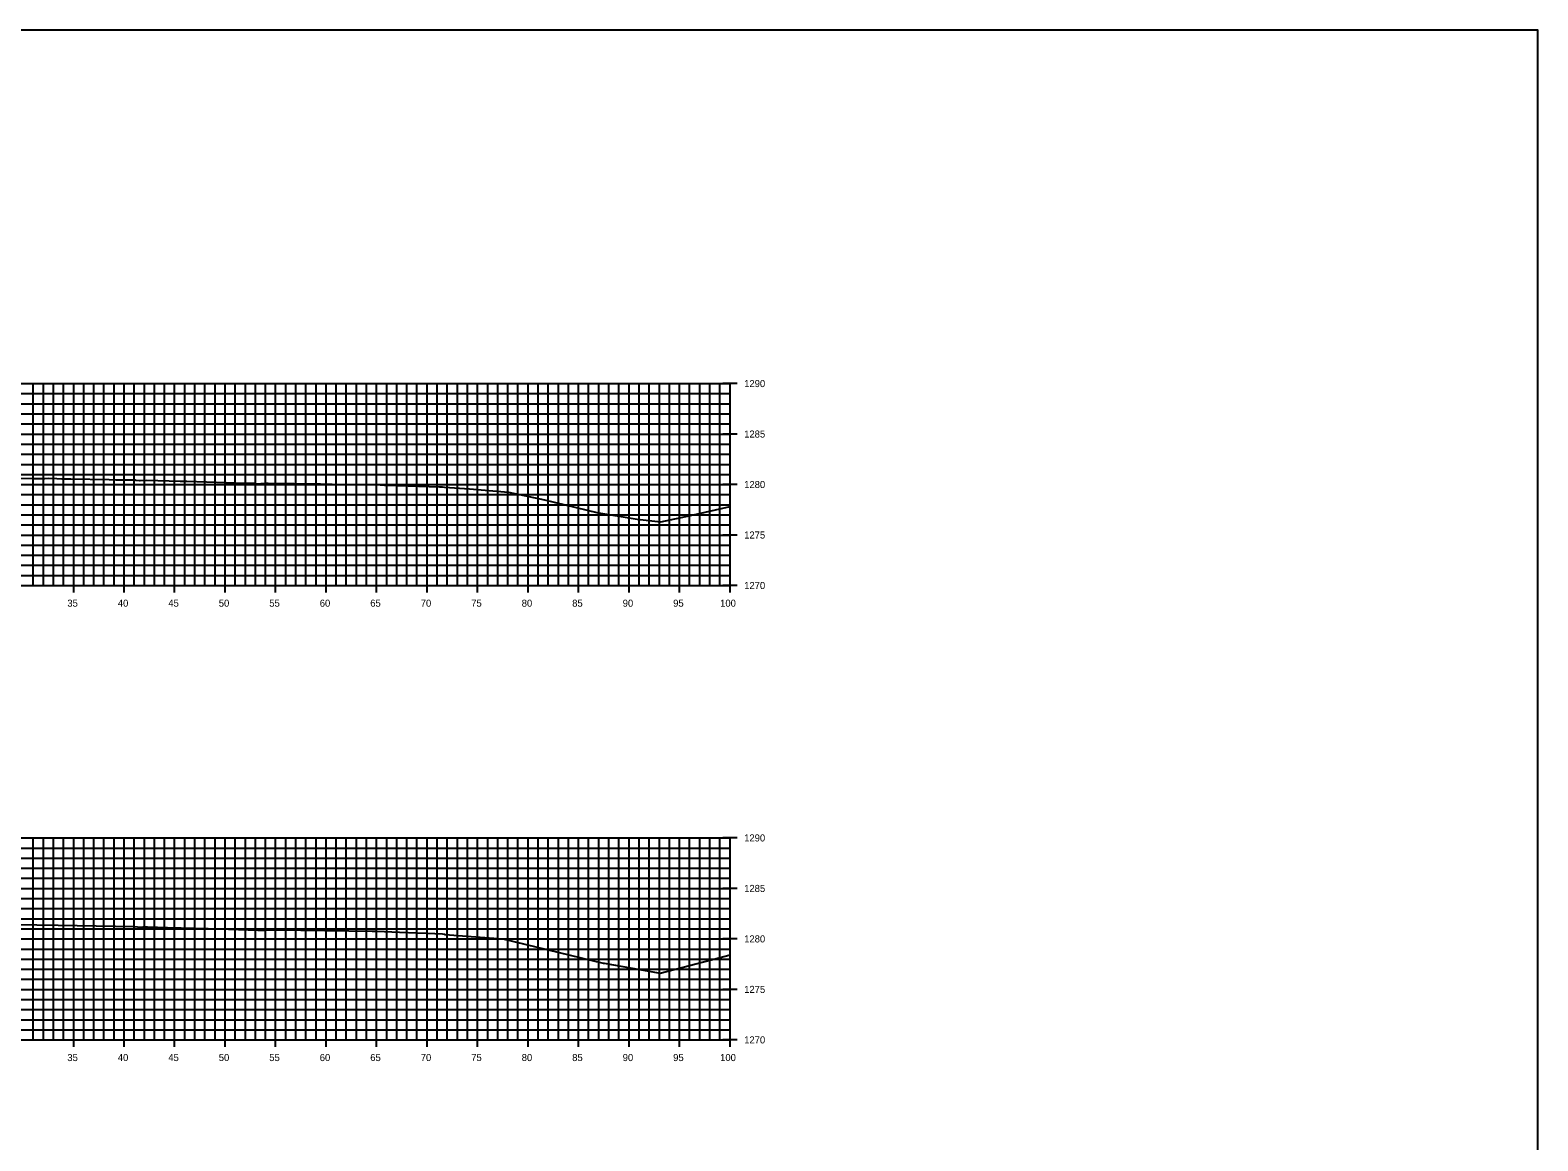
# Model space of a CAD drawing. Extents: x 674939 to 678919, y 750652 to 765176.
# Drawn here: x 678769.2 to 678918.5, y 759082.6 to 759192.6 of the extents above; entities that cross this region are included whole.
import ezdxf

# ---------------------------------------------------------------- set-up
doc = ezdxf.new("R2010")
doc.units = 0
for name, color, linetype in [('Level 10', 7, 'Continuous'), ('Level 20', 7, 'Continuous'), ('Level 4', 7, 'Continuous'), ('Level 8', 7, 'Continuous'), ('Level 9', 7, 'Continuous')]:
    doc.layers.add(name, color=color, linetype=linetype)

msp = doc.modelspace()

# ---------------------------------------------------------------- linework, layer by layer
at = {"layer": 'Level 10'}
for points in [[(678768.24, 759148.19), (678769.45, 759148.16), (678770.66, 759148.16), (678771, 759148.17), (678771.86, 759148.16), (678772.37, 759148.13), (678773.24, 759148.13), (678777.03, 759148.04), (678777.72, 759148.03), (678779.61, 759148), (678779.7, 759147.99), (678780.04, 759147.95), (678780.1, 759147.96), (678780.79, 759147.99), (678784.07, 759147.9), (678784.72, 759147.88), (678790.59, 759147.69), (678791.44, 759147.67), (678791.47, 759147.66), (678791.64, 759147.63), (678792.51, 759147.67), (678792.78, 759147.67), (678797.96, 759147.62), (678799.13, 759147.6), (678802.24, 759147.55), (678802.28, 759147.55), (678802.62, 759147.54), (678802.66, 759147.54), (678803.88, 759147.51), (678804.31, 759147.49), (678804.59, 759147.49), (678809.77, 759147.33), (678809.88, 759147.33), (678809.93, 759147.32), (678810.02, 759147.32), (678810.07, 759147.31), (678810.25, 759147.28), (678810.26, 759147.28), (678812.74, 759147.14), (678816.58, 759146.81), (678820.15, 759146.03), (678825.34, 759144.77), (678829.35, 759144.11), (678831.68, 759143.85), (678834.63, 759144.48), (678838.53, 759145.38)], [(678768.27, 759103.98), (678769.87, 759103.96), (678771.99, 759103.92), (678775.76, 759103.84), (678779.57, 759103.77), (678779.85, 759103.75), (678780.16, 759103.72), (678780.38, 759103.74), (678780.85, 759103.75), (678782.82, 759103.69), (678786.85, 759103.59), (678789.86, 759103.49), (678791.77, 759103.42), (678791.86, 759103.41), (678792.07, 759103.41), (678792.54, 759103.43), (678793.6, 759103.44), (678796.04, 759103.42), (678800.79, 759103.35), (678803.09, 759103.31), (678803.23, 759103.31), (678803.55, 759103.31), (678805.8, 759103.22), (678809.31, 759103.09), (678810.06, 759103.05), (678810.27, 759103.02), (678810.32, 759103), (678812.88, 759102.79), (678816.03, 759102.55), (678825.97, 759100.16), (678826.04, 759100.15), (678826.08, 759100.14), (678831.6, 759099.16), (678837.43, 759100.66), (678838.53, 759100.97)]]:
    msp.add_lwpolyline(points, dxfattribs=at)
at = {"layer": 'Level 20'}
for p, q in [((678638.53, 759157.55), (678838.53, 759157.55)), ((678769.53, 759137.55), (678769.53, 759157.55)), ((678770.53, 759137.55), (678770.53, 759157.55)), ((678771.53, 759137.55), (678771.53, 759157.55)), ((678772.53, 759137.55), (678772.53, 759157.55)), ((678773.53, 759137.55), (678773.53, 759157.55)), ((678774.53, 759137.55), (678774.53, 759157.55)), ((678775.53, 759137.55), (678775.53, 759157.55)), ((678776.53, 759137.55), (678776.53, 759157.55)), ((678777.53, 759137.55), (678777.53, 759157.55)), ((678778.53, 759137.55), (678778.53, 759157.55)), ((678779.53, 759137.55), (678779.53, 759157.55)), ((678780.53, 759137.55), (678780.53, 759157.55)), ((678781.53, 759137.55), (678781.53, 759157.55)), ((678782.53, 759137.55), (678782.53, 759157.55)), ((678783.53, 759137.55), (678783.53, 759157.55)), ((678784.53, 759137.55), (678784.53, 759157.55)), ((678785.53, 759137.55), (678785.53, 759157.55)), ((678786.53, 759137.55), (678786.53, 759157.55)), ((678787.53, 759137.55), (678787.53, 759157.55)), ((678788.53, 759137.55), (678788.53, 759157.55)), ((678789.53, 759137.55), (678789.53, 759157.55)), ((678790.53, 759137.55), (678790.53, 759157.55)), ((678791.53, 759137.55), (678791.53, 759157.55)), ((678792.53, 759137.55), (678792.53, 759157.55)), ((678793.53, 759137.55), (678793.53, 759157.55)), ((678794.53, 759137.55), (678794.53, 759157.55)), ((678795.53, 759137.55), (678795.53, 759157.55)), ((678796.53, 759137.55), (678796.53, 759157.55)), ((678797.53, 759137.55), (678797.53, 759157.55)), ((678798.53, 759137.55), (678798.53, 759157.55)), ((678799.53, 759137.55), (678799.53, 759157.55)), ((678800.53, 759137.55), (678800.53, 759157.55)), ((678801.53, 759137.55), (678801.53, 759157.55)), ((678802.53, 759137.55), (678802.53, 759157.55)), ((678803.53, 759137.55), (678803.53, 759157.55)), ((678804.53, 759137.55), (678804.53, 759157.55)), ((678805.53, 759137.55), (678805.53, 759157.55)), ((678806.53, 759137.55), (678806.53, 759157.55)), ((678807.53, 759137.55), (678807.53, 759157.55)), ((678808.53, 759137.55), (678808.53, 759157.55)), ((678809.53, 759137.55), (678809.53, 759157.55)), ((678810.53, 759137.55), (678810.53, 759157.55)), ((678811.53, 759137.55), (678811.53, 759157.55)), ((678812.53, 759137.55), (678812.53, 759157.55)), ((678813.53, 759137.55), (678813.53, 759157.55)), ((678814.53, 759137.55), (678814.53, 759157.55)), ((678815.53, 759137.55), (678815.53, 759157.55)), ((678816.53, 759137.55), (678816.53, 759157.55)), ((678817.53, 759137.55), (678817.53, 759157.55)), ((678818.53, 759137.55), (678818.53, 759157.55)), ((678819.53, 759137.55), (678819.53, 759157.55)), ((678820.53, 759137.55), (678820.53, 759157.55)), ((678821.53, 759137.55), (678821.53, 759157.55)), ((678822.53, 759137.55), (678822.53, 759157.55)), ((678823.53, 759137.55), (678823.53, 759157.55)), ((678824.53, 759137.55), (678824.53, 759157.55)), ((678825.53, 759137.55), (678825.53, 759157.55)), ((678826.53, 759137.55), (678826.53, 759157.55)), ((678827.53, 759137.55), (678827.53, 759157.55)), ((678828.53, 759137.55), (678828.53, 759157.55)), ((678829.53, 759137.55), (678829.53, 759157.55)), ((678830.53, 759137.55), (678830.53, 759157.55)), ((678831.53, 759137.55), (678831.53, 759157.55)), ((678832.53, 759137.55), (678832.53, 759157.55)), ((678833.53, 759137.55), (678833.53, 759157.55)), ((678834.53, 759137.55), (678834.53, 759157.55)), ((678835.53, 759137.55), (678835.53, 759157.55)), ((678836.53, 759137.55), (678836.53, 759157.55)), ((678837.53, 759137.55), (678837.53, 759157.55)), ((678838.53, 759137.55), (678838.53, 759157.55)), ((678638.53, 759156.55), (678838.53, 759156.55)), ((678638.53, 759155.55), (678838.53, 759155.55)), ((678638.53, 759154.55), (678838.53, 759154.55)), ((678638.53, 759153.55), (678838.53, 759153.55)), ((678638.53, 759152.55), (678838.53, 759152.55)), ((678638.53, 759151.55), (678838.53, 759151.55)), ((678638.53, 759150.55), (678838.53, 759150.55)), ((678638.53, 759149.55), (678838.53, 759149.55)), ((678638.53, 759148.55), (678838.53, 759148.55)), ((678638.53, 759147.55), (678838.53, 759147.55)), ((678638.53, 759146.55), (678838.53, 759146.55)), ((678638.53, 759145.55), (678838.53, 759145.55)), ((678638.53, 759144.55), (678838.53, 759144.55)), ((678638.53, 759143.55), (678838.53, 759143.55)), ((678638.53, 759142.55), (678838.53, 759142.55)), ((678638.53, 759141.55), (678838.53, 759141.55)), ((678638.53, 759140.55), (678838.53, 759140.55)), ((678638.53, 759139.55), (678838.53, 759139.55)), ((678638.53, 759138.55), (678838.53, 759138.55)), ((678638.53, 759137.55), (678838.53, 759137.55)), ((678638.53, 759112.55), (678838.53, 759112.55)), ((678769.53, 759092.55), (678769.53, 759112.55)), ((678770.53, 759092.55), (678770.53, 759112.55)), ((678771.53, 759092.55), (678771.53, 759112.55)), ((678772.53, 759092.55), (678772.53, 759112.55)), ((678773.53, 759092.55), (678773.53, 759112.55)), ((678774.53, 759092.55), (678774.53, 759112.55)), ((678775.53, 759092.55), (678775.53, 759112.55)), ((678776.53, 759092.55), (678776.53, 759112.55)), ((678777.53, 759092.55), (678777.53, 759112.55)), ((678778.53, 759092.55), (678778.53, 759112.55)), ((678779.53, 759092.55), (678779.53, 759112.55)), ((678780.53, 759092.55), (678780.53, 759112.55)), ((678781.53, 759092.55), (678781.53, 759112.55)), ((678782.53, 759092.55), (678782.53, 759112.55)), ((678783.53, 759092.55), (678783.53, 759112.55)), ((678784.53, 759092.55), (678784.53, 759112.55)), ((678785.53, 759092.55), (678785.53, 759112.55)), ((678786.53, 759092.55), (678786.53, 759112.55)), ((678787.53, 759092.55), (678787.53, 759112.55)), ((678788.53, 759092.55), (678788.53, 759112.55)), ((678789.53, 759092.55), (678789.53, 759112.55)), ((678790.53, 759092.55), (678790.53, 759112.55)), ((678791.53, 759092.55), (678791.53, 759112.55)), ((678792.53, 759092.55), (678792.53, 759112.55)), ((678793.53, 759092.55), (678793.53, 759112.55)), ((678794.53, 759092.55), (678794.53, 759112.55)), ((678795.53, 759092.55), (678795.53, 759112.55)), ((678796.53, 759092.55), (678796.53, 759112.55)), ((678797.53, 759092.55), (678797.53, 759112.55)), ((678798.53, 759092.55), (678798.53, 759112.55)), ((678799.53, 759092.55), (678799.53, 759112.55)), ((678800.53, 759092.55), (678800.53, 759112.55)), ((678801.53, 759092.55), (678801.53, 759112.55)), ((678802.53, 759092.55), (678802.53, 759112.55)), ((678803.53, 759092.55), (678803.53, 759112.55)), ((678804.53, 759092.55), (678804.53, 759112.55)), ((678805.53, 759092.55), (678805.53, 759112.55)), ((678806.53, 759092.55), (678806.53, 759112.55)), ((678807.53, 759092.55), (678807.53, 759112.55)), ((678808.53, 759092.55), (678808.53, 759112.55)), ((678809.53, 759092.55), (678809.53, 759112.55)), ((678810.53, 759092.55), (678810.53, 759112.55)), ((678811.53, 759092.55), (678811.53, 759112.55)), ((678812.53, 759092.55), (678812.53, 759112.55)), ((678813.53, 759092.55), (678813.53, 759112.55)), ((678814.53, 759092.55), (678814.53, 759112.55)), ((678815.53, 759092.55), (678815.53, 759112.55)), ((678816.53, 759092.55), (678816.53, 759112.55)), ((678817.53, 759092.55), (678817.53, 759112.55)), ((678818.53, 759092.55), (678818.53, 759112.55)), ((678819.53, 759092.55), (678819.53, 759112.55)), ((678820.53, 759092.55), (678820.53, 759112.55)), ((678821.53, 759092.55), (678821.53, 759112.55)), ((678822.53, 759092.55), (678822.53, 759112.55)), ((678823.53, 759092.55), (678823.53, 759112.55)), ((678824.53, 759092.55), (678824.53, 759112.55)), ((678825.53, 759092.55), (678825.53, 759112.55)), ((678826.53, 759092.55), (678826.53, 759112.55)), ((678827.53, 759092.55), (678827.53, 759112.55)), ((678828.53, 759092.55), (678828.53, 759112.55)), ((678829.53, 759092.55), (678829.53, 759112.55)), ((678830.53, 759092.55), (678830.53, 759112.55)), ((678831.53, 759092.55), (678831.53, 759112.55)), ((678832.53, 759092.55), (678832.53, 759112.55)), ((678833.53, 759092.55), (678833.53, 759112.55)), ((678834.53, 759092.55), (678834.53, 759112.55)), ((678835.53, 759092.55), (678835.53, 759112.55)), ((678836.53, 759092.55), (678836.53, 759112.55)), ((678837.53, 759092.55), (678837.53, 759112.55)), ((678838.53, 759092.55), (678838.53, 759112.55)), ((678638.53, 759111.55), (678838.53, 759111.55)), ((678638.53, 759110.55), (678838.53, 759110.55)), ((678638.53, 759109.55), (678838.53, 759109.55)), ((678638.53, 759108.55), (678838.53, 759108.55)), ((678638.53, 759107.55), (678838.53, 759107.55)), ((678638.53, 759106.55), (678838.53, 759106.55)), ((678638.53, 759105.55), (678838.53, 759105.55)), ((678638.53, 759104.55), (678838.53, 759104.55)), ((678638.53, 759103.55), (678838.53, 759103.55)), ((678638.53, 759102.55), (678838.53, 759102.55)), ((678638.53, 759101.55), (678838.53, 759101.55)), ((678638.53, 759100.55), (678838.53, 759100.55)), ((678638.53, 759099.55), (678838.53, 759099.55)), ((678638.53, 759098.55), (678838.53, 759098.55)), ((678638.53, 759097.55), (678838.53, 759097.55)), ((678638.53, 759096.55), (678838.53, 759096.55)), ((678638.53, 759095.55), (678838.53, 759095.55)), ((678638.53, 759094.55), (678838.53, 759094.55)), ((678638.53, 759093.55), (678838.53, 759093.55)), ((678638.53, 759092.55), (678838.53, 759092.55))]:
    msp.add_line(p, q, dxfattribs=at)
at = {"layer": 'Level 4'}
msp.add_lwpolyline([(678578.53, 758972.55), (678918.53, 758972.55), (678918.53, 759192.55), (678578.53, 759192.55)], close=True, dxfattribs=at)
at = {"layer": 'Level 8'}
for p, q in [((678839.23, 759157.55), (678837.83, 759157.55)), ((678838.53, 759137.55), (678838.53, 759157.55)), ((678839.23, 759152.55), (678837.83, 759152.55)), ((678839.23, 759147.55), (678837.83, 759147.55)), ((678839.23, 759142.55), (678837.83, 759142.55)), ((678638.53, 759137.55), (678838.53, 759137.55)), ((678773.53, 759136.85), (678773.53, 759138.25)), ((678778.53, 759136.85), (678778.53, 759138.25)), ((678783.53, 759136.85), (678783.53, 759138.25)), ((678788.53, 759136.85), (678788.53, 759138.25)), ((678793.53, 759136.85), (678793.53, 759138.25)), ((678798.53, 759136.85), (678798.53, 759138.25)), ((678803.53, 759136.85), (678803.53, 759138.25)), ((678808.53, 759136.85), (678808.53, 759138.25)), ((678813.53, 759136.85), (678813.53, 759138.25)), ((678818.53, 759136.85), (678818.53, 759138.25)), ((678823.53, 759136.85), (678823.53, 759138.25)), ((678828.53, 759136.85), (678828.53, 759138.25)), ((678833.53, 759136.85), (678833.53, 759138.25)), ((678839.23, 759137.55), (678837.83, 759137.55)), ((678838.53, 759136.85), (678838.53, 759138.25)), ((678839.23, 759112.55), (678837.83, 759112.55)), ((678838.53, 759092.55), (678838.53, 759112.55)), ((678839.23, 759107.55), (678837.83, 759107.55)), ((678839.23, 759102.55), (678837.83, 759102.55)), ((678839.23, 759097.55), (678837.83, 759097.55)), ((678638.53, 759092.55), (678838.53, 759092.55)), ((678773.53, 759091.85), (678773.53, 759093.25)), ((678778.53, 759091.85), (678778.53, 759093.25)), ((678783.53, 759091.85), (678783.53, 759093.25)), ((678788.53, 759091.85), (678788.53, 759093.25)), ((678793.53, 759091.85), (678793.53, 759093.25)), ((678798.53, 759091.85), (678798.53, 759093.25)), ((678803.53, 759091.85), (678803.53, 759093.25)), ((678808.53, 759091.85), (678808.53, 759093.25)), ((678813.53, 759091.85), (678813.53, 759093.25)), ((678818.53, 759091.85), (678818.53, 759093.25)), ((678823.53, 759091.85), (678823.53, 759093.25)), ((678828.53, 759091.85), (678828.53, 759093.25)), ((678833.53, 759091.85), (678833.53, 759093.25)), ((678839.23, 759092.55), (678837.83, 759092.55)), ((678838.53, 759091.85), (678838.53, 759093.25))]:
    msp.add_line(p, q, dxfattribs=at)

# ---------------------------------------------------------------- texts
at = {"layer": 'Level 9'}
for s, p in [('1290', (678839.93, 759157.2)), ('1285', (678839.93, 759152.2)), ('1280', (678839.93, 759147.2)), ('1275', (678839.93, 759142.2)), ('1270', (678839.93, 759137.2)), ('35', (678772.9, 759135.45)), ('40', (678777.9, 759135.45)), ('45', (678782.9, 759135.45)), ('50', (678787.9, 759135.45)), ('55', (678792.9, 759135.45)), ('60', (678797.9, 759135.45)), ('65', (678802.9, 759135.45)), ('70', (678807.9, 759135.45)), ('75', (678812.9, 759135.45)), ('80', (678817.9, 759135.45)), ('85', (678822.9, 759135.45)), ('90', (678827.9, 759135.45)), ('95', (678832.9, 759135.45)), ('100', (678837.55, 759135.45)), ('1290', (678839.93, 759112.2)), ('1285', (678839.93, 759107.2)), ('1280', (678839.93, 759102.2)), ('1275', (678839.93, 759097.2)), ('1270', (678839.93, 759092.2)), ('35', (678772.9, 759090.45)), ('40', (678777.9, 759090.45)), ('45', (678782.9, 759090.45)), ('50', (678787.9, 759090.45)), ('55', (678792.9, 759090.45)), ('60', (678797.9, 759090.45)), ('65', (678802.9, 759090.45)), ('70', (678807.9, 759090.45)), ('75', (678812.9, 759090.45)), ('80', (678817.9, 759090.45)), ('85', (678822.9, 759090.45)), ('90', (678827.9, 759090.45)), ('95', (678832.9, 759090.45)), ('100', (678837.55, 759090.45))]:
    msp.add_text(s, height=0.7, dxfattribs=at).set_placement(p)

doc.saveas('drawing.dxf')
